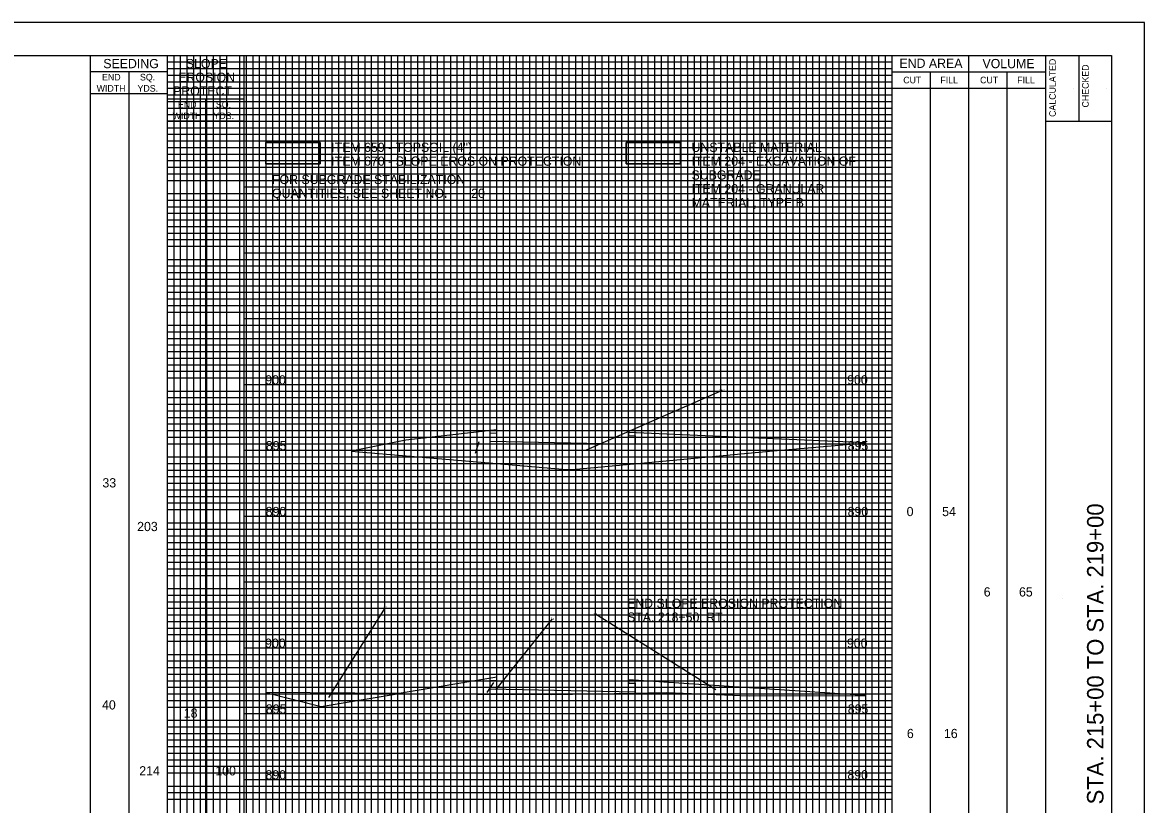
# Model space of a CAD drawing. Extents: x -73 to 160, y -2 to 1877.
# Drawn here: x 74.8 to 160, y 1773.1 to 1832.5 of the extents above; entities that cross this region are included whole.
import ezdxf

# ---------------------------------------------------------------- set-up
doc = ezdxf.new("R2010")
doc.units = 0
for name, color, linetype in [('DR_P_Flood_Boundary', 7, 'Continuous'), ('GK_Cells', 7, 'Continuous'), ('PV_P_Drive', 7, 'Continuous'), ('PV_P_EOP', 7, 'Continuous'), ('RD_X_Fence', 7, 'Continuous'), ('TX_X_5', 7, 'Continuous'), ('UT_P_Water_Cells', 7, 'Continuous'), ('XS_P_Pavt_Surface', 7, 'Continuous'), ('XS_P_Special_Benching', 7, 'Continuous'), ('XS_X_Ground_Line', 7, 'Continuous')]:
    doc.layers.add(name, color=color, linetype=linetype)

msp = doc.modelspace()

# ---------------------------------------------------------------- linework, layer by layer
at = {"layer": 'DR_P_Flood_Boundary'}
for p, q in [((95.832, 1725), (95.832, 1830)), ((100.832, 1725), (100.832, 1830)), ((105.832, 1725), (105.832, 1830)), ((110.832, 1725), (110.832, 1830)), ((115.832, 1725), (115.832, 1830)), ((120.832, 1725), (120.832, 1830)), ((125.832, 1725), (125.832, 1830)), ((130.832, 1725), (130.832, 1830)), ((135.832, 1725), (135.832, 1830)), ((85.832, 1825), (140.832, 1825)), ((91.665, 1820), (140.832, 1820)), ((91.665, 1815), (140.832, 1815)), ((91.665, 1810), (140.832, 1810)), ((91.665, 1805), (140.832, 1805)), ((91.665, 1800), (140.832, 1800)), ((91.665, 1795), (140.832, 1795)), ((91.665, 1790), (140.832, 1790)), ((91.665, 1785), (140.832, 1785)), ((91.665, 1780), (140.832, 1780)), ((91.665, 1775), (140.832, 1775))]:
    msp.add_line(p, q, dxfattribs=at)
at = {"layer": 'GK_Cells'}
for p, q in [((152.5, 1725), (152.5, 1830)), ((155, 1830), (155, 1825)), ((152.5, 1825), (157.5, 1825))]:
    msp.add_line(p, q, dxfattribs=at)
msp.add_lwpolyline([(0, 1830), (157.5, 1830), (157.5, 1725), (0, 1725)], close=True, dxfattribs=at)
at = {"layer": 'PV_P_Drive'}
msp.add_lwpolyline([(93.295, 1823.379), (97.435, 1823.379), (97.435, 1821.763), (93.295, 1821.763)], close=True, dxfattribs=at)
msp.add_lwpolyline([(93.295, 1821.763), (97.435, 1821.763), (97.435, 1823.379), (93.295, 1823.379), (93.295, 1821.763)], dxfattribs=at)
at = {"layer": 'PV_P_EOP'}
msp.add_lwpolyline([(120.644, 1823.379), (124.784, 1823.379), (124.784, 1821.763), (120.644, 1821.763)], close=True, dxfattribs=at)
msp.add_lwpolyline([(120.644, 1821.763), (124.784, 1821.763), (124.784, 1823.379), (120.644, 1823.379), (120.644, 1821.763)], dxfattribs=at)
at = {"layer": 'RD_X_Fence'}
for p, q in [((117.633, 1800.048), (127.96, 1804.568)), ((110.832, 1801.563), (103.923, 1800.77)), ((103.923, 1800.77), (99.783, 1799.942)), ((109.225, 1799.777), (109.487, 1800.663)), ((110.332, 1800.657), (110.332, 1801.323)), ((110.332, 1801.323), (110.832, 1801.313)), ((121.332, 1800.437), (110.332, 1800.657)), ((138.832, 1800.564), (120.832, 1801.363)), ((120.832, 1801.113), (121.332, 1801.103)), ((121.332, 1801.103), (121.332, 1800.437)), ((99.783, 1799.942), (109.332, 1799.124)), ((109.332, 1799.124), (116.12, 1798.543)), ((116.572, 1798.53), (122.332, 1799.075)), ((116.12, 1798.543), (116.572, 1798.53)), ((98.073, 1781.221), (102.384, 1788.051)), ((110.771, 1781.797), (115.059, 1787.205)), ((127.457, 1781.804), (118.327, 1787.544)), ((110.832, 1782.764), (103.415, 1781.528)), ((110.1, 1781.61), (110.601, 1782.372)), ((110.284, 1781.889), (110.332, 1781.964)), ((110.332, 1781.964), (110.332, 1782.524)), ((110.332, 1782.524), (110.832, 1782.514)), ((121.332, 1781.637), (110.332, 1781.857)), ((138.787, 1781.38), (120.832, 1782.564)), ((120.832, 1782.314), (121.332, 1782.304)), ((121.332, 1782.304), (121.332, 1781.637)), ((93.298, 1781.594), (97.504, 1780.542)), ((103.415, 1781.528), (93.298, 1781.594)), ((97.504, 1780.542), (103.415, 1781.528)), ((103.415, 1781.528), (109.332, 1781.489)), ((109.332, 1781.489), (114.975, 1781.452)), ((114.975, 1781.452), (121.334, 1781.554))]:
    msp.add_line(p, q, dxfattribs=at)
for points in [[(110.832, 1801.313), (110.832, 1801.459), (110.832, 1801.563)], [(120.832, 1801.363), (120.832, 1801.259), (120.832, 1801.113)], [(122.332, 1799.075), (131.533, 1799.945), (138.832, 1800.564)], [(110.832, 1782.514), (110.832, 1782.66), (110.832, 1782.764)], [(110.332, 1781.857), (110.284, 1781.889)], [(120.832, 1782.564), (120.832, 1782.46), (120.832, 1782.314)], [(121.332, 1781.637), (121.334, 1781.554)], [(121.334, 1781.554), (121.332, 1781.637)], [(121.334, 1781.554), (122.332, 1781.57), (123.732, 1781.593)], [(123.732, 1781.593), (129.981, 1781.361), (138.787, 1781.38)]]:
    msp.add_lwpolyline(points, dxfattribs=at)
at = {"layer": 'TX_X_5'}
msp.add_lwpolyline([(-10, 1722.5), (160, 1722.5), (160, 1832.5), (-10, 1832.5)], close=True, dxfattribs=at)
at = {"layer": 'UT_P_Water_Cells'}
for p, q in [((86.332, 1725), (86.332, 1830)), ((86.832, 1725), (86.832, 1830)), ((87.332, 1725), (87.332, 1830)), ((87.832, 1725), (87.832, 1830)), ((88.332, 1725), (88.332, 1830)), ((88.832, 1725), (88.832, 1830)), ((89.332, 1725), (89.332, 1830)), ((89.832, 1725), (89.832, 1830)), ((90.332, 1725), (90.332, 1830)), ((91.332, 1725), (91.332, 1830)), ((91.832, 1725), (91.832, 1830)), ((92.332, 1725), (92.332, 1830)), ((92.832, 1725), (92.832, 1830)), ((93.332, 1725), (93.332, 1830)), ((93.832, 1725), (93.832, 1830)), ((94.332, 1725), (94.332, 1830)), ((94.832, 1725), (94.832, 1830)), ((95.332, 1725), (95.332, 1830)), ((96.332, 1725), (96.332, 1830)), ((96.832, 1725), (96.832, 1830)), ((97.332, 1725), (97.332, 1830)), ((97.832, 1725), (97.832, 1830)), ((98.332, 1725), (98.332, 1830)), ((98.832, 1725), (98.832, 1830)), ((99.332, 1725), (99.332, 1830)), ((99.832, 1725), (99.832, 1830)), ((100.332, 1725), (100.332, 1830)), ((101.332, 1725), (101.332, 1830)), ((101.832, 1725), (101.832, 1830)), ((102.332, 1725), (102.332, 1830)), ((102.832, 1725), (102.832, 1830)), ((103.332, 1725), (103.332, 1830)), ((103.832, 1725), (103.832, 1830)), ((104.332, 1725), (104.332, 1830)), ((104.832, 1725), (104.832, 1830)), ((105.332, 1725), (105.332, 1830)), ((106.332, 1725), (106.332, 1830)), ((106.832, 1725), (106.832, 1830)), ((107.332, 1725), (107.332, 1830)), ((107.832, 1725), (107.832, 1830)), ((108.332, 1725), (108.332, 1830)), ((108.832, 1725), (108.832, 1830)), ((109.332, 1725), (109.332, 1830)), ((109.832, 1725), (109.832, 1830)), ((110.332, 1725), (110.332, 1830)), ((111.332, 1725), (111.332, 1830)), ((111.832, 1725), (111.832, 1830)), ((112.332, 1725), (112.332, 1830)), ((112.832, 1725), (112.832, 1830)), ((113.332, 1725), (113.332, 1830)), ((113.832, 1725), (113.832, 1830)), ((114.332, 1725), (114.332, 1830)), ((114.832, 1725), (114.832, 1830)), ((115.332, 1725), (115.332, 1830)), ((116.332, 1725), (116.332, 1830)), ((116.832, 1725), (116.832, 1830)), ((117.332, 1725), (117.332, 1830)), ((117.832, 1725), (117.832, 1830)), ((118.332, 1725), (118.332, 1830)), ((118.832, 1725), (118.832, 1830)), ((119.332, 1725), (119.332, 1830)), ((119.832, 1725), (119.832, 1830)), ((120.332, 1725), (120.332, 1830)), ((121.332, 1725), (121.332, 1830)), ((121.832, 1725), (121.832, 1830)), ((122.332, 1725), (122.332, 1830)), ((122.832, 1725), (122.832, 1830)), ((123.332, 1725), (123.332, 1830)), ((123.832, 1725), (123.832, 1830)), ((124.332, 1725), (124.332, 1830)), ((124.832, 1725), (124.832, 1830)), ((125.332, 1725), (125.332, 1830)), ((126.332, 1725), (126.332, 1830)), ((126.832, 1725), (126.832, 1830)), ((127.332, 1725), (127.332, 1830)), ((127.832, 1725), (127.832, 1830)), ((128.332, 1725), (128.332, 1830)), ((128.832, 1725), (128.832, 1830)), ((129.332, 1725), (129.332, 1830)), ((129.832, 1725), (129.832, 1830)), ((130.332, 1725), (130.332, 1830)), ((131.332, 1725), (131.332, 1830)), ((131.832, 1725), (131.832, 1830)), ((132.332, 1725), (132.332, 1830)), ((132.832, 1725), (132.832, 1830)), ((133.332, 1725), (133.332, 1830)), ((133.832, 1725), (133.832, 1830)), ((134.332, 1725), (134.332, 1830)), ((134.832, 1725), (134.832, 1830)), ((135.332, 1725), (135.332, 1830)), ((136.332, 1725), (136.332, 1830)), ((136.832, 1725), (136.832, 1830)), ((137.332, 1725), (137.332, 1830)), ((137.832, 1725), (137.832, 1830)), ((138.332, 1725), (138.332, 1830)), ((138.832, 1725), (138.832, 1830)), ((139.332, 1725), (139.332, 1830)), ((139.832, 1725), (139.832, 1830)), ((140.332, 1725), (140.332, 1830)), ((85.832, 1829.5), (140.832, 1829.5)), ((85.832, 1829), (140.832, 1829)), ((85.832, 1828.5), (140.832, 1828.5)), ((85.832, 1828), (140.832, 1828)), ((85.832, 1827.5), (140.832, 1827.5)), ((85.832, 1827), (140.832, 1827)), ((85.832, 1826.5), (140.832, 1826.5)), ((85.832, 1826), (140.832, 1826)), ((85.832, 1825.5), (140.832, 1825.5)), ((85.832, 1824.5), (140.832, 1824.5)), ((85.832, 1824), (140.832, 1824)), ((85.832, 1823.5), (140.832, 1823.5)), ((85.832, 1823), (140.832, 1823)), ((85.832, 1822.5), (140.832, 1822.5)), ((85.832, 1822), (140.832, 1822)), ((85.832, 1821.5), (140.832, 1821.5)), ((85.832, 1821), (140.832, 1821)), ((85.832, 1820.5), (140.832, 1820.5)), ((85.832, 1819.5), (140.832, 1819.5)), ((85.832, 1819), (140.832, 1819)), ((85.832, 1818.5), (140.832, 1818.5)), ((85.832, 1818), (140.832, 1818)), ((85.832, 1817.5), (140.832, 1817.5)), ((85.832, 1817), (140.832, 1817)), ((85.832, 1816.5), (140.832, 1816.5)), ((85.832, 1816), (140.832, 1816)), ((85.832, 1815.5), (140.832, 1815.5)), ((85.832, 1814.5), (140.832, 1814.5)), ((85.832, 1814), (140.832, 1814)), ((85.832, 1813.5), (140.832, 1813.5)), ((85.832, 1813), (140.832, 1813)), ((85.832, 1812.5), (140.832, 1812.5)), ((85.832, 1812), (140.832, 1812)), ((85.832, 1811.5), (140.832, 1811.5)), ((85.832, 1811), (140.832, 1811)), ((85.832, 1810.5), (140.832, 1810.5)), ((85.832, 1809.5), (140.832, 1809.5)), ((85.832, 1809), (140.832, 1809)), ((85.832, 1808.5), (140.832, 1808.5)), ((85.832, 1808), (140.832, 1808)), ((85.832, 1807.5), (140.832, 1807.5)), ((85.832, 1807), (140.832, 1807)), ((85.832, 1806.5), (140.832, 1806.5)), ((85.832, 1806), (140.832, 1806)), ((85.832, 1805.5), (140.832, 1805.5)), ((85.832, 1804.5), (140.832, 1804.5)), ((85.832, 1804), (140.832, 1804)), ((85.832, 1803.5), (140.832, 1803.5)), ((85.832, 1803), (140.832, 1803)), ((85.832, 1802.5), (140.832, 1802.5)), ((85.832, 1802), (140.832, 1802)), ((85.832, 1801.5), (140.832, 1801.5)), ((85.832, 1801), (140.832, 1801)), ((85.832, 1800.5), (140.832, 1800.5)), ((85.832, 1799.5), (140.832, 1799.5)), ((85.832, 1799), (140.832, 1799)), ((85.832, 1798.5), (140.832, 1798.5)), ((85.832, 1798), (140.832, 1798)), ((85.832, 1797.5), (140.832, 1797.5)), ((85.832, 1797), (140.832, 1797)), ((85.832, 1796.5), (140.832, 1796.5)), ((85.832, 1796), (140.832, 1796)), ((85.832, 1795.5), (140.832, 1795.5)), ((85.832, 1794.5), (140.832, 1794.5)), ((85.832, 1794), (140.832, 1794)), ((85.832, 1793.5), (140.832, 1793.5)), ((85.832, 1793), (140.832, 1793)), ((85.832, 1792.5), (140.832, 1792.5)), ((85.832, 1792), (140.832, 1792)), ((85.832, 1791.5), (140.832, 1791.5)), ((85.832, 1791), (140.832, 1791)), ((85.832, 1790.5), (140.832, 1790.5)), ((85.832, 1789.5), (140.832, 1789.5)), ((85.832, 1789), (140.832, 1789)), ((85.832, 1788.5), (140.832, 1788.5)), ((85.832, 1788), (140.832, 1788)), ((85.832, 1787.5), (140.832, 1787.5)), ((85.832, 1787), (140.832, 1787)), ((85.832, 1786.5), (140.832, 1786.5)), ((85.832, 1786), (140.832, 1786)), ((85.832, 1785.5), (140.832, 1785.5)), ((85.832, 1784.5), (140.832, 1784.5)), ((85.832, 1784), (140.832, 1784)), ((85.832, 1783.5), (140.832, 1783.5)), ((85.832, 1783), (140.832, 1783)), ((85.832, 1782.5), (140.832, 1782.5)), ((85.832, 1782), (140.832, 1782)), ((85.832, 1781.5), (140.832, 1781.5)), ((85.832, 1781), (140.832, 1781)), ((85.832, 1780.5), (140.832, 1780.5)), ((85.832, 1779.5), (140.832, 1779.5)), ((85.832, 1779), (140.832, 1779)), ((85.832, 1778.5), (140.832, 1778.5)), ((85.832, 1778), (140.832, 1778)), ((85.832, 1777.5), (140.832, 1777.5)), ((85.832, 1777), (140.832, 1777)), ((85.832, 1776.5), (140.832, 1776.5)), ((85.832, 1776), (140.832, 1776)), ((85.832, 1775.5), (140.832, 1775.5)), ((85.832, 1774.5), (140.832, 1774.5)), ((85.832, 1774), (140.832, 1774)), ((85.832, 1773.5), (140.832, 1773.5))]:
    msp.add_line(p, q, dxfattribs=at)
at = {"layer": 'XS_X_Ground_Line'}
for p, q in [((80, 1725), (80, 1830)), ((85.832, 1725), (85.832, 1830)), ((85.832, 1725), (85.832, 1830)), ((91.665, 1725), (91.665, 1830)), ((140.832, 1725), (140.832, 1830)), ((146.667, 1725), (146.667, 1830)), ((85.832, 1828.75), (80, 1828.75)), ((82.916, 1725), (82.916, 1828.75)), ((140.832, 1828.75), (152.5, 1828.75)), ((143.75, 1725), (143.75, 1828.75)), ((149.583, 1725), (149.583, 1828.75)), ((85.832, 1827.083), (80, 1827.083)), ((140.832, 1827.5), (152.5, 1827.5)), ((154.6, 1827.518), (154.6, 1827.518)), ((157.1, 1827.518), (157.1, 1827.518)), ((91.665, 1826.667), (85.832, 1826.667)), ((88.749, 1725), (88.749, 1826.667)), ((91.665, 1825), (85.832, 1825)), ((153.75, 1788.75), (153.75, 1788.75)), ((156.258, 1788.75), (156.258, 1788.75))]:
    msp.add_line(p, q, dxfattribs=at)

# ---------------------------------------------------------------- texts
at = {"layer": 'RD_X_Fence'}
for s, p in [('11.9', (106.647, 1819.294)), ('54.3', (127.739, 1804.498)), ('5.2', (102.226, 1787.981)), ('7.1', (114.926, 1787.135)), ('9.2', (118.168, 1787.474))]:
    msp.add_text(s, height=0.14, dxfattribs=at).set_placement(p)
at = {"layer": 'XS_P_Pavt_Surface'}
for s, p in [('900', (93.259, 1805)), ('900', (137.427, 1805)), ('895', (93.303, 1800)), ('895', (137.471, 1800)), ('33', (80.899, 1797.179)), ('890', (93.292, 1795)), ('890', (137.46, 1795)), ('0', (141.941, 1795)), ('54', (144.637, 1795)), ('203', (83.533, 1793.862)), ('6', (147.794, 1788.895)), ('65', (150.47, 1788.895)), ('END SLOPE EROSION PROTECTION', (120.719, 1788.029)), ('STA. 218+50, RT.', (120.719, 1786.979)), ('900', (93.243, 1785)), ('900', (137.41, 1785)), ('40', (80.869, 1780.312)), ('18', (87.074, 1779.693)), ('895', (93.303, 1780)), ('895', (137.471, 1780)), ('6', (141.961, 1778.14)), ('16', (144.772, 1778.14)), ('214', (83.693, 1775.304)), ('100', (89.468, 1775.304)), ('890', (93.276, 1775)), ('890', (137.443, 1775))]:
    msp.add_text(s, height=0.7, dxfattribs=at).set_placement(p)
at = {"layer": 'XS_P_Special_Benching'}
for s, p in [('ITEM 659 - TOPSOIL (4")', (98.263, 1822.665)), ('UNSTABLE MATERIAL', (125.612, 1822.665)), ('ITEM 670 - SLOPE EROSION PROTECTION', (98.263, 1821.615)), ('ITEM 204 - EXCAVATION OF', (125.612, 1821.615)), ('SUBGRADE', (125.612, 1820.565)), ('FOR SUBGRADE STABILIZATION', (93.77, 1820.223)), ('ITEM 204 - GRANULAR', (125.612, 1819.515)), ('QUANTITIES, SEE SHEET NO.', (93.77, 1819.173)), ('20', (108.888, 1819.173)), ('MATERIAL, TYPE B', (125.612, 1818.465))]:
    msp.add_text(s, height=0.7, dxfattribs=at).set_placement(p)
at = {"layer": 'XS_X_Ground_Line'}
for s, height, p in [('SEEDING', 0.7, (80.964, 1829.025)), ('SLOPE', 0.7, (87.228, 1829.025)), ('END AREA', 0.7, (141.394, 1829.047)), ('VOLUME', 0.7, (147.698, 1829.025)), ('EROSION', 0.7, (86.649, 1827.983)), ('END', 0.5, (80.87, 1828.092)), ('SQ.', 0.5, (83.748, 1828.092)), ('CUT', 0.5, (141.683, 1827.875)), ('FILL', 0.5, (144.502, 1827.875)), ('CUT', 0.5, (147.517, 1827.875)), ('FILL', 0.5, (150.335, 1827.875)), ('WIDTH', 0.5, (80.462, 1827.242)), ('YDS.', 0.5, (83.563, 1827.242)), ('PROTECT.', 0.7, (86.26, 1826.942)), ('END', 0.5, (86.631, 1826.008)), ('SQ.', 0.5, (89.51, 1826.008)), ('WIDTH', 0.5, (86.224, 1825.158)), ('YDS.', 0.5, (89.325, 1825.158))]:
    msp.add_text(s, height=height, dxfattribs=at).set_placement(p)
for s, height, p in [('CALCULATED', 0.5, (153.262, 1825.323)), ('CHECKED', 0.5, (155.762, 1826.04)), ('STA. 215+00 TO STA. 219+00', 1.25, (156.883, 1773.105))]:
    msp.add_text(s, height=height, rotation=90, dxfattribs=at).set_placement(p)

doc.saveas('drawing.dxf')
